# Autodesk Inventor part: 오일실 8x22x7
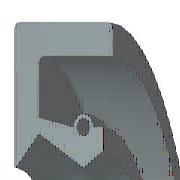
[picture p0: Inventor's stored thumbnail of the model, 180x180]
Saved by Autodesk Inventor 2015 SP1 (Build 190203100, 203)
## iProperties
IsCustomPart: 1
Company: 한국ATC센터
Created: 2014-07
Part Number: 오일실 8x22x7
Material: 고무
Description: 오일-실
Document SubType Name: Modeling
Standard: KS B 2804
Designer: KYOUNG IL JANG
Standards Organization: KS
Language: ko-KR
Size Designation: D - 8 22 7
Categories: <MemberInstance><Categories><Category DisplayName="샤프트 부품" InternalName="7f7aeb1f-a693-4053-b835-cee3144e0d98" Mnemonic="SHFT"><Category DisplayName="실링" Intern
Density: 0.93 g/cm^3
Appearance: 고무 - 검은색 - 버전 1.1
Author: KYOUNG IL JANG
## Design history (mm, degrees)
revolve "본체" stored, may be unused: angle "d17" = 90 deg
revolve "스프링1" stored, may be unused: angle "d18" = 90 deg
body "Solid1"
sketch "스케치1"
  geometry: L1 (0, 11)-(7, 11); L2 (7, 9.25)-(1.75, 9.25); L3 (1.75, 5.75)-(4.9, 4); L4 (4.9, 4)-(0, 4); L5 (0, 0)-(9.586, 0) reference; L6 (4.9, 4)-(6.3, 4.875); L7 (0, 18)-(0, -3) reference; L8 (-1.941, 0)-(11.507, 0) reference; L9 (4.2, 6.1)-(1.75, 6.59); L10 (1.75, 6.59)-(1.75, 9.25); L11 (0, 11)-(0, 4.088); L12 (4.9, 4)-(0, 4); L13 (1.75, 5.75)-(0.152, 4.028); L14 (7, 11)-(7, 9.25); L15 (5.6, 6.1)-(6.3, 6.1); L16 (6.3, 6.1)-(6.3, 4.875); C1 r 0.455 at (4.9, 6.1); A1 r 0.7 centre (4.9, 6.1) between (5.6, 6.1) and (4.2, 6.1); A2 r 0.088 centre (0.088, 4.088) between (0, 4.088) and (0.152, 4.028); 1 further point
  constraints: 28 end point, 5 horizontal alignment, 5 point on line, 4 point on circle, 4 vertical alignment, 3 centre point, 3 tangent, 2 collinear, 2 horizontal, 2 perpendicular, 1 coincident, 1 parallel
  dimensions: "d0" = 22 diameter of L1 L5 (= SD2); "d1" = 1.75 distance of L1.end L2.start (= SD); "d2" = 0.91 diameter of C1 (= SPDI); "d3" = 1.4 diameter of A1 (= SPDA); "d4" = 8 diameter of L3.end L5 (= NND); "d5" = 11.5 diameter of L3.start L5 (= TKDM); "d7" = 13.18 diameter of L9.end L5 (= TKDM + 0.24 x SWDT); "d8" = 1.75 distance between parallel lines of L11 L10 (= SD); "d9" = 4.9 distance from line of L11 C1.centre (= SPDST); "d10" = 12.2 diameter of C1.centre L5 (= HLDM); "d11" = 0.0875 radius of A2 (= 0.25 x LAB); "d12" = 6.3 distance between parallel lines of L11 L16 (= SDI); "d13" = 9.75 diameter of L6.end L5 (= ABDM); "d14" = 7 distance from line of L11 L1.end (= SWDT)
fillet "모깎기1" dims "d6" = 0.3 (= RR)
other parameters: "SD2" = 22 [user parameter; used in 1 equation term], "SWDT" = 7 [user parameter; used in 2 equation terms], "RR" = 0.3 [user parameter; used in 1 equation term], "SD" = 1.75 [user parameter; used in 2 equation terms], "NND" = 8 [user parameter; used in 1 equation term], "SPDA" = 1.4 [user parameter; used in 1 equation term], "SPDI" = 0.91 [user parameter; used in 1 equation term], "TKDM" = 11.5 [user parameter; used in 2 equation terms], "HLDM" = 12.2 [user parameter; used in 1 equation term], "ABDM" = 9.75 [user parameter; used in 1 equation term], "SDI" = 6.3 [user parameter; used in 1 equation term], "SPDST" = 4.9 [user parameter; used in 1 equation term], "LAB" = 0.35 [user parameter; used in 1 equation term], "d15" = 0, "d16" = 0, "d19" = 0
